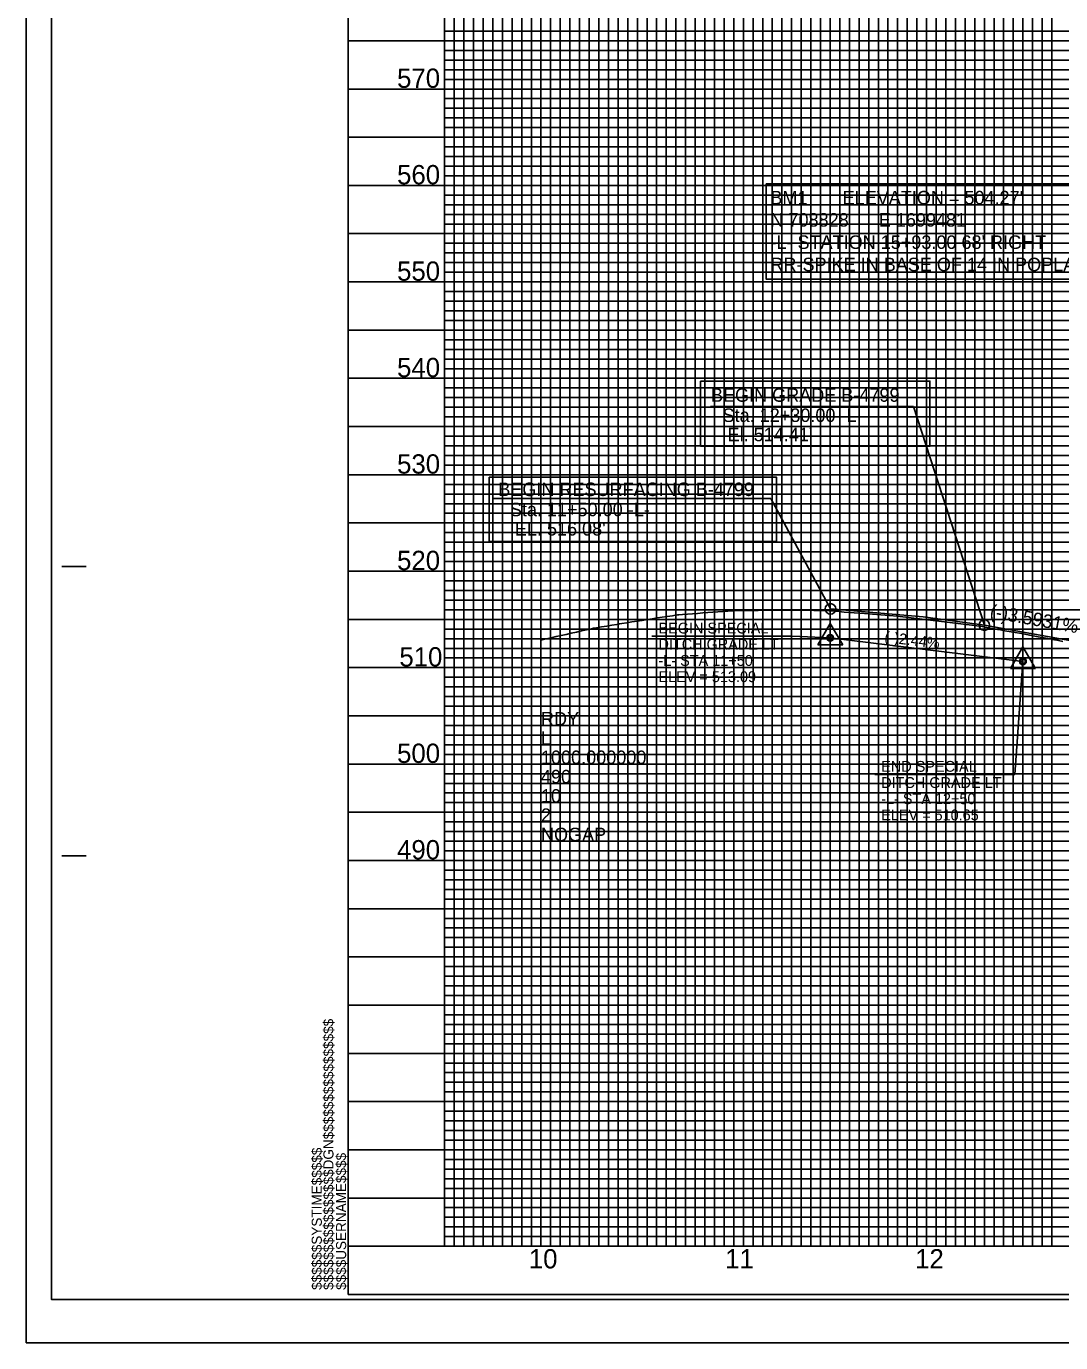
# Model space of a CAD drawing. Extents: x 573715 to 575626, y -55474 to -54374.
# Drawn here: x 573715 to 574252, y -55474 to -54792 of the extents above; entities that cross this region are included whole.
import ezdxf

# ---------------------------------------------------------------- set-up
doc = ezdxf.new("R2010")
doc.units = 0
for name, color, linetype in [('Exist Profile Cell', 7, 'Continuous'), ('Exist Vertical Profile Ground Line', 7, 'Continuous'), ('Exist Vertical Profile Horizontal Axis Label Major', 7, 'Continuous'), ('Exist Vertical Profile Vertical Axis Label', 7, 'Continuous'), ('Prop Grid Mask', 7, 'Continuous'), ('Prop PFL VPI Symbol CELL', 7, 'Continuous'), ('Prop Vertical Profile Curve Label', 7, 'Continuous'), ('Prop Vertical Profile Ditch Grade Left', 7, 'Continuous'), ('Prop Vertical Profile Ditch Grade Left Label', 7, 'Continuous'), ('Prop Vertical Profile Grade', 7, 'Continuous'), ('Prop Vertical Profile Grade Label', 7, 'Continuous'), ('Prop VPI Label', 7, 'Continuous'), ('Sheet Cutting Line CELL', 7, 'Continuous'), ('Sheet DOT Grid CELL', 7, 'Continuous'), ('Sheet Layout Profile Border', 7, 'Continuous'), ('Sheet Plot Border Inside CELL', 7, 'Continuous'), ('Sheet Plot Border Outside CELL', 7, 'Continuous'), ('Sheet Profile CELL', 7, 'Continuous'), ('Sheet Profile Grid Major CELL', 7, 'Continuous'), ('Sheet Profile Grid Middle CELL', 7, 'Continuous'), ('Sheet Profile Grid Minor CELL', 7, 'Continuous')]:
    doc.layers.add(name, color=color, linetype=linetype)

msp = doc.modelspace()

# ---------------------------------------------------------------- linework, layer by layer
at = {"layer": 'Exist Profile Cell'}
for q in [(573982.27, -54974.42), (575001.21, -55224.42), (573982.27, -55224.42)]:
    msp.add_line((573982.27, -55224.42), q, dxfattribs=at)
at = {"layer": 'Exist Vertical Profile Ground Line'}
msp.add_lwpolyline([(573982.27, -55110.15), (573984.9, -55109.54), (573987.52, -55108.95), (573990.14, -55108.35), (573992.76, -55107.76), (573995.38, -55107.17), (573998, -55106.58), (574000.62, -55106), (574003.24, -55105.42), (574005.86, -55104.84), (574008.49, -55104.27), (574009.58, -55104.02), (574011.11, -55103.76), (574013.73, -55103.32), (574016.35, -55102.88), (574018.97, -55102.44), (574021.59, -55102.01), (574022.51, -55101.86), (574023.06, -55101.77), (574024.21, -55101.58), (574026.83, -55101.16), (574029.45, -55100.74), (574032.08, -55100.32), (574034.7, -55099.91), (574037.32, -55099.5), (574039.94, -55099.09), (574042.56, -55098.69), (574045.18, -55098.29), (574047.8, -55097.9), (574050.42, -55097.51), (574051.85, -55097.29), (574053.04, -55097.12), (574053.74, -55097.06), (574055.67, -55096.9), (574058.29, -55096.69), (574060.91, -55096.49), (574063.53, -55096.28), (574066.15, -55096.09), (574068.77, -55095.89), (574071.39, -55095.7), (574074.01, -55095.51), (574076.63, -55095.33), (574079.26, -55095.15), (574081.88, -55094.97), (574082.66, -55094.92), (574083.74, -55094.85), (574084.5, -55094.84), (574087.12, -55094.8), (574089.74, -55094.77), (574092.36, -55094.74), (574094.98, -55094.72), (574097.06, -55094.7), (574097.81, -55094.71), (574100.23, -55094.69), (574102.85, -55094.68), (574105.47, -55094.67), (574108.09, -55094.67), (574110.71, -55094.67), (574113.33, -55094.67), (574115.95, -55094.68), (574118.57, -55094.69), (574121.19, -55094.71), (574123.82, -55094.72), (574126.44, -55094.75), (574127.38, -55094.76), (574127.79, -55094.76), (574129.06, -55094.85), (574131.68, -55095.03), (574134.3, -55095.22), (574136.92, -55095.4), (574138.22, -55095.5), (574139.54, -55095.59), (574142.16, -55095.79), (574144.78, -55095.99), (574147.41, -55096.19), (574150.03, -55096.4), (574154.32, -55096.74), (574158.56, -55097.08), (574162.89, -55097.45), (574167.18, -55097.81), (574168.42, -55097.93), (574171.47, -55098.28), (574175.76, -55098.78), (574180.05, -55099.29), (574184.34, -55099.8), (574188.63, -55100.31), (574192.92, -55100.83), (574197.21, -55101.36), (574201.5, -55101.89), (574205.79, -55102.42), (574208.37, -55102.75), (574210.22, -55103), (574214.37, -55103.74), (574218.66, -55104.5), (574219.21, -55104.6), (574220.63, -55104.84), (574222.95, -55105.26), (574227.24, -55106.03), (574231.52, -55106.81), (574235.81, -55107.6), (574240.1, -55108.38), (574244.39, -55109.18), (574248.68, -55109.98), (574249.19, -55110.07), (574252.97, -55110.89)], dxfattribs=at)
at = {"layer": 'Prop Grid Mask'}
for points in [[(574099.04, -54873.65), (574330.5, -54873.65), (574330.5, -54923), (574099.04, -54923)], [(574065.07, -54975.88), (574184.04, -54975.88), (574184.04, -55009.64), (574065.07, -55009.64)], [(573955.41, -55025.68), (574104.45, -55025.68), (574104.45, -55059.09), (573955.41, -55059.09)]]:
    msp.add_lwpolyline(points, close=True, dxfattribs=at)
at = {"layer": 'Prop PFL VPI Symbol CELL'}
for p, q in [((574132.27, -55101.49), (574125.82, -55112.69)), ((574132.27, -55101.49), (574138.77, -55112.69)), ((574125.82, -55112.69), (574138.77, -55112.69)), ((574232.27, -55113.69), (574225.82, -55124.89)), ((574232.27, -55113.69), (574238.77, -55124.89)), ((574225.82, -55124.89), (574238.77, -55124.89))]:
    msp.add_line(p, q, dxfattribs=at)
for centre, radius in [((574132.27, -55108.97), 1.75), ((574132.27, -55108.97), 1.2), ((574232.27, -55121.17), 1.75), ((574232.27, -55121.17), 1.2)]:
    msp.add_circle(centre, radius, dxfattribs=at)
at = {"layer": 'Prop Vertical Profile Curve Label'}
for p, q in [((574175.55, -54989.04), (574070.12, -54989.04)), ((574212.27, -55102.37), (574175.55, -54989.04)), ((574101.48, -55036.8), (573957.83, -55036.8)), ((574101.48, -55036.8), (574132.43, -55093.97))]:
    msp.add_line(p, q, dxfattribs=at)
at = {"layer": 'Prop Vertical Profile Ditch Grade Left'}
msp.add_line((574132.27, -55108.97), (574232.27, -55121.17), dxfattribs=at)
at = {"layer": 'Prop Vertical Profile Ditch Grade Left Label'}
for p, q in [((574039.84, -55108.14), (574112.49, -55108.14)), ((574112.49, -55108.14), (574132.27, -55108.97)), ((574232.27, -55121.17), (574228.02, -55179.82)), ((574155.37, -55179.82), (574228.02, -55179.82))]:
    msp.add_line(p, q, dxfattribs=at)
at = {"layer": 'Prop Vertical Profile Grade'}
for p, q in [((574132.43, -55093.97), (574180.44, -55098.13)), ((574180.44, -55098.13), (574212.27, -55102.37)), ((574212.27, -55102.37), (574262.27, -55111.35))]:
    msp.add_line(p, q, dxfattribs=at)
at = {"layer": 'Prop VPI Label'}
for centre in [(574132.43, -55093.97), (574212.27, -55102.37), (574212.27, -55102.37)]:
    msp.add_circle(centre, 2.75, dxfattribs=at)
at = {"layer": 'Sheet Cutting Line CELL'}
for p, q in [((573715.27, -54374.42), (573715.27, -55474.42)), ((573715.27, -54374.42), (573715.27, -55474.42)), ((573715.27, -55474.42), (575399.27, -55474.42))]:
    msp.add_line(p, q, dxfattribs=at)
at = {"layer": 'Sheet DOT Grid CELL'}
for p, q in [((573932.27, -54399.42), (573932.27, -55424.42)), ((573982.27, -54399.42), (573982.27, -55424.42)), ((574032.27, -54399.42), (574032.27, -55424.42)), ((574082.27, -54399.42), (574082.27, -55424.42)), ((574132.27, -54399.42), (574132.27, -55424.42)), ((574182.27, -54399.42), (574182.27, -55424.42)), ((574232.27, -54399.42), (574232.27, -55424.42)), ((573882.27, -54824.42), (575382.27, -54824.42)), ((573882.27, -54874.42), (575382.27, -54874.42)), ((573882.27, -54924.42), (575382.27, -54924.42)), ((573882.27, -54974.42), (575382.27, -54974.42)), ((573882.27, -55024.42), (575382.27, -55024.42)), ((573882.27, -55074.42), (575382.27, -55074.42)), ((573882.27, -55124.42), (575382.27, -55124.42)), ((573882.27, -55174.42), (575382.27, -55174.42)), ((573882.27, -55224.42), (575382.27, -55224.42)), ((573882.27, -55274.42), (575382.27, -55274.42)), ((573882.27, -55324.42), (575382.27, -55324.42)), ((573882.27, -55374.42), (575382.27, -55374.42))]:
    msp.add_line(p, q, dxfattribs=at)
at = {"layer": 'Sheet Layout Profile Border'}
msp.add_lwpolyline([(573932.27, -54399.42), (573932.27, -55424.42), (575332.27, -55424.42), (575332.27, -54536.97), (575182.22, -54536.97), (575182.22, -54399.42)], close=True, dxfattribs=at)
at = {"layer": 'Sheet Plot Border Inside CELL'}
msp.add_lwpolyline([(575394.77, -54396.87), (573728.27, -54396.87), (573728.27, -55451.97), (575394.77, -55451.97)], close=True, dxfattribs=at)
msp.add_lwpolyline([(575394.77, -54396.87), (573728.27, -54396.87), (573728.27, -55451.97), (575394.77, -55451.97)], close=True, dxfattribs=at)
at = {"layer": 'Sheet Plot Border Outside CELL'}
msp.add_lwpolyline([(575399.27, -54374.42), (573715.27, -54374.42), (573715.27, -55474.42), (575399.27, -55474.42)], close=True, dxfattribs=at)
at = {"layer": 'Sheet Profile CELL'}
for p, q in [((573733.77, -55071.92), (573746.27, -55071.92)), ((573733.77, -55221.92), (573746.27, -55221.92)), ((575382.27, -55424.42), (573882.27, -55424.42)), ((573882.27, -55449.42), (573882.27, -55449.42)), ((573882.27, -55449.42), (573882.27, -55449.42)), ((573882.27, -55449.42), (573882.27, -55449.42)), ((573882.27, -55449.42), (573882.27, -55449.42)), ((573882.27, -55449.42), (573882.27, -55449.42)), ((573882.27, -55449.42), (573882.27, -55449.42)), ((573882.27, -55449.42), (573882.27, -55449.42)), ((573882.27, -55449.42), (573882.27, -55449.42)), ((573882.27, -55449.42), (573882.27, -55449.42)), ((573882.27, -55449.42), (573882.27, -55449.42)), ((573882.27, -55449.42), (573882.27, -55449.42)), ((573882.27, -55449.42), (573882.27, -55449.42))]:
    msp.add_line(p, q, dxfattribs=at)
msp.add_lwpolyline([(575382.27, -54399.42), (573882.27, -54399.42), (573882.27, -55449.42), (575382.27, -55449.42)], close=True, dxfattribs=at)
msp.add_lwpolyline([(573919.77, -55449.42), (573919.77, -55449.42)], dxfattribs=at)
msp.add_lwpolyline([(573919.77, -55449.42), (573919.77, -55449.42)], dxfattribs=at)
at = {"layer": 'Sheet Profile Grid Major CELL'}
for points in [[(573882.27, -54399.42), (573932.27, -54399.42), (573932.27, -55424.42), (573982.27, -55424.42), (573982.27, -54399.42), (574032.27, -54399.42), (574032.27, -55424.42), (574082.27, -55424.42), (574082.27, -54399.42), (574132.27, -54399.42), (574132.27, -55424.42), (574182.27, -55424.42), (574182.27, -54399.42), (574232.27, -54399.42), (574232.27, -55424.42), (574282.27, -55424.42)], [(575382.27, -54874.42), (573882.27, -54874.42), (573882.27, -54824.42), (575382.27, -54824.42)], [(575382.27, -54974.42), (573882.27, -54974.42), (573882.27, -54924.42), (575382.27, -54924.42)], [(575382.27, -55074.42), (573882.27, -55074.42), (573882.27, -55024.42), (575382.27, -55024.42)], [(575382.27, -55174.42), (573882.27, -55174.42), (573882.27, -55124.42), (575382.27, -55124.42)], [(575382.27, -55274.42), (573882.27, -55274.42), (573882.27, -55224.42), (575382.27, -55224.42)], [(575382.27, -55374.42), (573882.27, -55374.42), (573882.27, -55324.42), (575382.27, -55324.42)]]:
    msp.add_lwpolyline(points, dxfattribs=at)
at = {"layer": 'Sheet Profile Grid Middle CELL'}
for points in [[(573957.27, -55424.42), (573957.27, -54399.42), (574007.27, -54399.42), (574007.27, -55424.42), (574057.27, -55424.42), (574057.27, -54399.42), (574107.27, -54399.42), (574107.27, -55424.42), (574157.27, -55424.42), (574157.27, -54399.42), (574207.27, -54399.42), (574207.27, -55424.42), (574257.27, -55424.42)], [(575382.27, -54799.42), (573882.27, -54799.42), (573882.27, -54849.42), (575382.27, -54849.42)], [(575382.27, -54899.42), (573882.27, -54899.42), (573882.27, -54949.42), (575382.27, -54949.42)], [(575382.27, -54999.42), (573882.27, -54999.42), (573882.27, -55049.42), (575382.27, -55049.42)], [(575382.27, -55099.42), (573882.27, -55099.42), (573882.27, -55149.42), (575382.27, -55149.42)], [(575382.27, -55199.42), (573882.27, -55199.42), (573882.27, -55249.42), (575382.27, -55249.42)], [(575382.27, -55299.42), (573882.27, -55299.42), (573882.27, -55349.42), (575382.27, -55349.42)], [(575382.27, -55399.42), (573882.27, -55399.42)]]:
    msp.add_lwpolyline(points, dxfattribs=at)
at = {"layer": 'Sheet Profile Grid Minor CELL'}
for points in [[(573937.27, -54399.42), (573937.27, -55424.42), (573942.27, -55424.42), (573942.27, -54399.42)], [(573947.27, -54399.42), (573947.27, -55424.42), (573952.27, -55424.42), (573952.27, -54399.42)], [(573962.27, -54399.42), (573962.27, -55424.42), (573967.27, -55424.42), (573967.27, -54399.42)], [(573972.27, -54399.42), (573972.27, -55424.42), (573977.27, -55424.42), (573977.27, -54399.42)], [(573987.27, -54399.42), (573987.27, -55424.42), (573992.27, -55424.42), (573992.27, -54399.42)], [(573997.27, -54399.42), (573997.27, -55424.42), (574002.27, -55424.42), (574002.27, -54399.42)], [(574012.27, -54399.42), (574012.27, -55424.42), (574017.27, -55424.42), (574017.27, -54399.42)], [(574022.27, -54399.42), (574022.27, -55424.42), (574027.27, -55424.42), (574027.27, -54399.42)], [(574037.27, -54399.42), (574037.27, -55424.42), (574042.27, -55424.42), (574042.27, -54399.42)], [(574047.27, -54399.42), (574047.27, -55424.42), (574052.27, -55424.42), (574052.27, -54399.42)], [(574062.27, -54399.42), (574062.27, -55424.42), (574067.27, -55424.42), (574067.27, -54399.42)], [(574072.27, -54399.42), (574072.27, -55424.42), (574077.27, -55424.42), (574077.27, -54399.42)], [(574087.27, -54399.42), (574087.27, -55424.42), (574092.27, -55424.42), (574092.27, -54399.42)], [(574097.27, -55424.42), (574102.27, -55424.42), (574102.27, -54399.42)], [(574097.27, -54399.42), (574097.27, -55424.42)], [(574112.27, -54399.42), (574112.27, -55424.42), (574117.27, -55424.42), (574117.27, -54399.42)], [(574122.27, -54399.42), (574122.27, -55424.42), (574127.27, -55424.42), (574127.27, -54399.42)], [(574137.27, -54399.42), (574137.27, -55424.42), (574142.27, -55424.42), (574142.27, -54399.42)], [(574147.27, -54399.42), (574147.27, -55424.42), (574152.27, -55424.42), (574152.27, -54399.42)], [(574162.27, -54399.42), (574162.27, -55424.42), (574167.27, -55424.42), (574167.27, -54399.42)], [(574172.27, -54399.42), (574172.27, -55424.42), (574177.27, -55424.42), (574177.27, -54399.42)], [(574187.27, -54399.42), (574187.27, -55424.42), (574192.27, -55424.42), (574192.27, -54399.42)], [(574197.27, -54399.42), (574197.27, -55424.42), (574202.27, -55424.42), (574202.27, -54399.42)], [(574212.27, -54399.42), (574212.27, -55424.42), (574217.27, -55424.42), (574217.27, -54399.42)], [(574222.27, -54399.42), (574222.27, -55424.42), (574227.27, -55424.42), (574227.27, -54399.42)], [(574237.27, -54399.42), (574237.27, -55424.42), (574242.27, -55424.42), (574242.27, -54399.42)], [(574247.27, -54399.42), (574247.27, -55424.42), (574252.27, -55424.42)], [(575332.27, -54794.42), (573932.27, -54794.42), (573932.27, -54804.42), (575332.27, -54804.42)], [(575332.27, -54809.42), (573932.27, -54809.42), (573932.27, -54814.42), (575332.27, -54814.42)], [(575332.27, -54819.42), (573932.27, -54819.42), (573932.27, -54829.42), (575332.27, -54829.42)], [(575332.27, -54834.42), (573932.27, -54834.42), (573932.27, -54839.42), (575332.27, -54839.42)], [(575332.27, -54844.42), (573932.27, -54844.42), (573932.27, -54854.42), (575332.27, -54854.42)], [(575332.27, -54859.42), (573932.27, -54859.42), (573932.27, -54864.42), (575332.27, -54864.42)], [(575332.27, -54869.42), (573932.27, -54869.42), (573932.27, -54879.42), (575332.27, -54879.42)], [(575332.27, -54884.42), (573932.27, -54884.42), (573932.27, -54889.42), (575332.27, -54889.42)], [(575332.27, -54894.42), (573932.27, -54894.42), (573932.27, -54904.42), (575332.27, -54904.42)], [(575332.27, -54909.42), (573932.27, -54909.42), (573932.27, -54914.42), (575332.27, -54914.42)], [(575332.27, -54919.42), (573932.27, -54919.42)], [(573932.27, -54929.42), (575332.27, -54929.42)], [(575332.27, -54934.42), (573932.27, -54934.42), (573932.27, -54939.42), (575332.27, -54939.42)], [(575332.27, -54944.42), (573932.27, -54944.42), (573932.27, -54954.42), (575332.27, -54954.42)], [(575332.27, -54959.42), (573932.27, -54959.42), (573932.27, -54964.42), (575332.27, -54964.42)], [(575332.27, -54969.42), (573932.27, -54969.42), (573932.27, -54979.42), (575332.27, -54979.42)], [(575332.27, -54984.42), (573932.27, -54984.42), (573932.27, -54989.42), (575332.27, -54989.42)], [(575332.27, -54994.42), (573932.27, -54994.42), (573932.27, -55004.42), (575332.27, -55004.42)], [(575332.27, -55009.42), (573932.27, -55009.42), (573932.27, -55014.42), (575332.27, -55014.42)], [(575332.27, -55019.42), (573932.27, -55019.42), (573932.27, -55029.42), (575332.27, -55029.42)], [(575332.27, -55034.42), (573932.27, -55034.42), (573932.27, -55039.42), (575332.27, -55039.42)], [(575332.27, -55044.42), (573932.27, -55044.42), (573932.27, -55054.42), (575332.27, -55054.42)], [(575332.27, -55059.42), (573932.27, -55059.42), (573932.27, -55064.42), (575332.27, -55064.42)], [(575332.27, -55069.42), (573932.27, -55069.42), (573932.27, -55079.42), (575332.27, -55079.42)], [(575332.27, -55084.42), (573932.27, -55084.42), (573932.27, -55089.42), (575332.27, -55089.42)], [(575332.27, -55094.42), (573932.27, -55094.42), (573932.27, -55104.42), (575332.27, -55104.42)], [(575332.27, -55109.42), (573932.27, -55109.42), (573932.27, -55114.42), (575332.27, -55114.42)], [(575332.27, -55119.42), (573932.27, -55119.42), (573932.27, -55129.42), (575332.27, -55129.42)], [(575332.27, -55134.42), (573932.27, -55134.42), (573932.27, -55139.42), (575332.27, -55139.42)], [(575332.27, -55144.42), (573932.27, -55144.42), (573932.27, -55154.42), (575332.27, -55154.42)], [(575332.27, -55159.42), (573932.27, -55159.42), (573932.27, -55164.42), (575332.27, -55164.42)], [(575332.27, -55169.42), (573932.27, -55169.42), (573932.27, -55179.42), (575332.27, -55179.42)], [(575332.27, -55184.42), (573932.27, -55184.42), (573932.27, -55189.42), (575332.27, -55189.42)], [(575332.27, -55194.42), (573932.27, -55194.42), (573932.27, -55204.42), (575332.27, -55204.42)], [(575332.27, -55209.42), (573932.27, -55209.42), (573932.27, -55214.42), (575332.27, -55214.42)], [(575332.27, -55219.42), (573932.27, -55219.42)], [(573932.27, -55229.42), (575332.27, -55229.42)], [(575332.27, -55234.42), (573932.27, -55234.42), (573932.27, -55239.42), (575332.27, -55239.42)], [(575332.27, -55244.42), (573932.27, -55244.42)], [(573932.27, -55254.42), (575332.27, -55254.42)], [(575332.27, -55259.42), (573932.27, -55259.42), (573932.27, -55264.42), (575332.27, -55264.42)], [(575332.27, -55269.42), (573932.27, -55269.42), (573932.27, -55279.42), (575332.27, -55279.42)], [(575332.27, -55284.42), (573932.27, -55284.42), (573932.27, -55289.42), (575332.27, -55289.42)], [(575332.27, -55294.42), (573932.27, -55294.42), (573932.27, -55304.42), (575332.27, -55304.42)], [(575332.27, -55309.42), (573932.27, -55309.42), (573932.27, -55314.42), (575332.27, -55314.42)], [(575332.27, -55319.42), (573932.27, -55319.42), (573932.27, -55329.42), (575332.27, -55329.42)], [(575332.27, -55334.42), (573932.27, -55334.42), (573932.27, -55339.42), (575332.27, -55339.42)], [(575332.27, -55344.42), (573932.27, -55344.42), (573932.27, -55354.42), (575332.27, -55354.42)], [(575332.27, -55359.42), (573932.27, -55359.42), (573932.27, -55364.42), (575332.27, -55364.42)], [(575332.27, -55369.42), (573932.27, -55369.42), (573932.27, -55379.42), (575332.27, -55379.42)], [(575332.27, -55384.42), (573932.27, -55384.42), (573932.27, -55389.42), (575332.27, -55389.42)], [(575332.27, -55394.42), (573932.27, -55394.42), (573932.27, -55404.42), (575332.27, -55404.42)], [(575332.27, -55409.42), (573932.27, -55409.42), (573932.27, -55414.42), (575332.27, -55414.42)], [(575332.27, -55419.42), (573932.27, -55419.42)]]:
    msp.add_lwpolyline(points, dxfattribs=at)

# ---------------------------------------------------------------- texts
at = {"layer": 'Exist Profile Cell'}
for s, p in [('RDY', (573982.27, -55154.42)), ('L', (573982.27, -55164.42)), ('1000.000000', (573982.27, -55174.42)), ('490', (573982.27, -55184.42)), ('10', (573982.27, -55194.42)), ('2', (573982.27, -55204.42)), ('NOGAP', (573982.27, -55214.42))]:
    msp.add_text(s, height=7, dxfattribs=at).set_placement(p)
at = {"layer": 'Exist Vertical Profile Horizontal Axis Label Major'}
for s, p in [('10', (573975.96, -55435.92)), ('12', (574176.35, -55435.92)), ('11', (574077.8, -55435.92))]:
    msp.add_text(s, height=10, dxfattribs=at).set_placement(p)
at = {"layer": 'Exist Vertical Profile Vertical Axis Label'}
for s, p in [('570', (573907.61, -54823.83)), ('560', (573907.61, -54873.83)), ('550', (573907.61, -54923.83)), ('540', (573907.61, -54973.83)), ('530', (573907.61, -55023.83)), ('520', (573907.61, -55073.83)), ('510', (573908.81, -55123.83)), ('500', (573907.61, -55173.83)), ('490', (573907.61, -55223.83))]:
    msp.add_text(s, height=10, dxfattribs=at).set_placement(p)
at = {"layer": 'Prop Vertical Profile Curve Label'}
for s, p in [('BEGIN GRADE B-4799', (574070.45, -54986.59)), ('Sta. 12+30.00 -L-', (574076.47, -54997.05)), (" El. 514.41'", (574076.47, -55007.05)), ('BEGIN RESURFACING B-4799', (573960.1, -55035.46)), ('Sta. 11+50.00 -L-', (573966.11, -55045.93)), (" EL. 516.08'", (573966.11, -55055.93))]:
    msp.add_text(s, height=7, dxfattribs=at).set_placement(p)
at = {"layer": 'Prop Vertical Profile Ditch Grade Left'}
msp.add_text('(-)2.44%', height=5.6, rotation=353.00171, dxfattribs=at).set_placement((574160.23, -55111.15))
at = {"layer": 'Prop Vertical Profile Ditch Grade Left Label'}
for s, p in [('BEGIN SPECIAL', (574043.22, -55106.72)), ('DITCH GRADE LT', (574043.22, -55115.12)), ('-L- STA 11+50', (574043.22, -55123.52)), ('ELEV = 513.09', (574043.22, -55131.92)), ('END SPECIAL', (574158.76, -55178.41)), ('DITCH GRADE LT', (574158.76, -55186.81)), ('-L- STA 12+50', (574158.76, -55195.21)), ('ELEV = 510.65', (574158.76, -55203.61))]:
    msp.add_text(s, height=5.6, dxfattribs=at).set_placement(p)
at = {"layer": 'Prop Vertical Profile Grade Label'}
msp.add_text('(-)3.5931%', height=7, rotation=349.81516, dxfattribs=at).set_placement((574214.75, -55098.46))
at = {"layer": 'Prop VPI Label'}
for s, p in [("BM1       ELEVATION = 504.27'", (574101.29, -54884.23)), ('N 708828      E 1699481', (574101.29, -54895.78)), ("-L- STATION 15+93.00 68' RIGHT", (574101.29, -54907.33)), ('RR-SPIKE IN BASE OF 14 IN POPLAR TREE', (574101.29, -54918.88))]:
    msp.add_text(s, height=7, dxfattribs=at).set_placement(p)
at = {"layer": 'Sheet Profile CELL'}
for s, p in [('$$$$$$$$$$$$$$$$DGN$$$$$$$$$$$$$$$$', (573874.62, -55447.06)), ('$$$$$$SYSTIME$$$$$', (573868.57, -55447.06)), ('$$$$USERNAME$$$$', (573881.2, -55447.05))]:
    msp.add_text(s, height=5.25, rotation=90, dxfattribs=at).set_placement(p)

doc.saveas('drawing.dxf')
